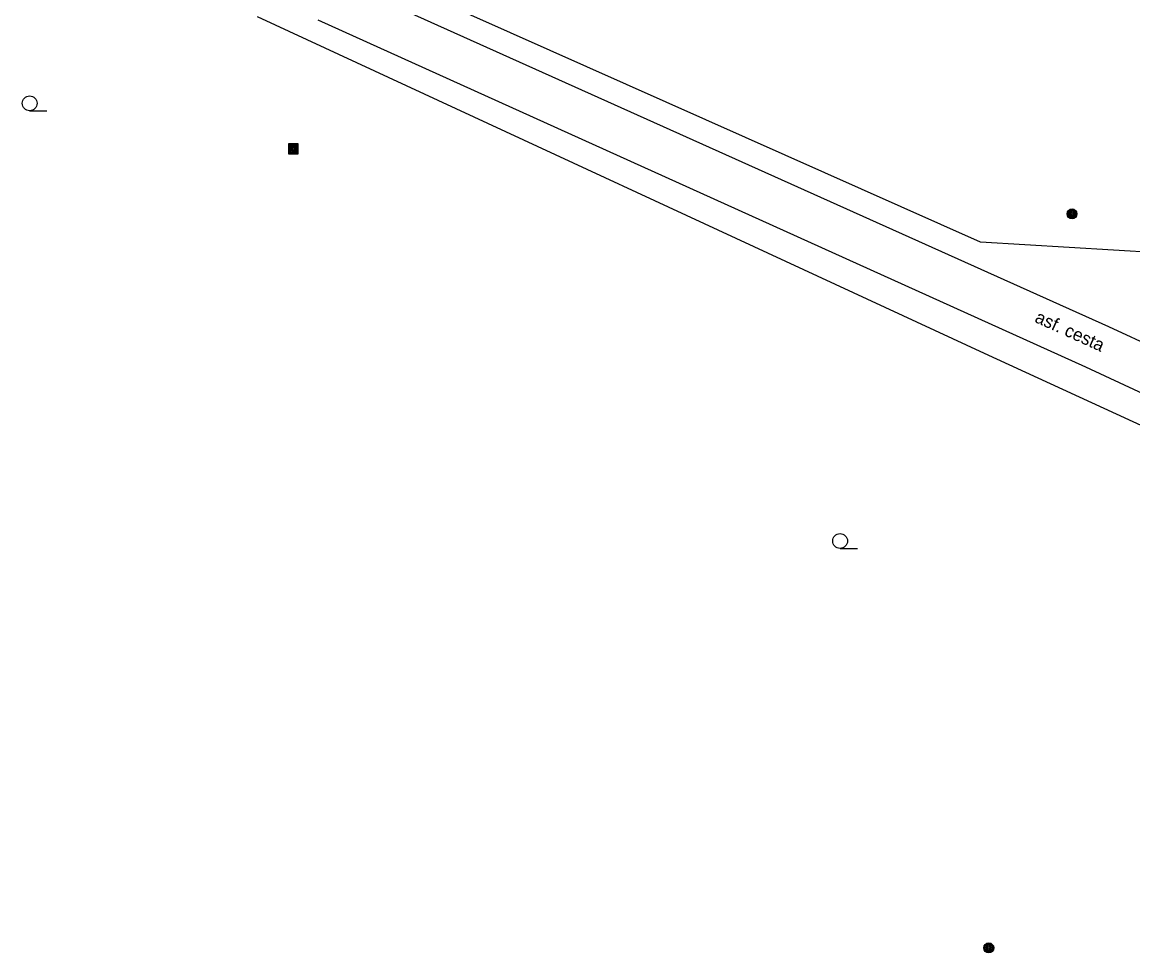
# Model space of a CAD drawing. Extents: x -538441 to -536770, y -1181008 to -1179809.
# Drawn here: x -537623 to -537566.8, y -1180346.7 to -1180299.6 of the extents above; entities that cross this region are included whole.
import ezdxf

# ---------------------------------------------------------------- set-up
doc = ezdxf.new("R2010")
doc.units = 0
for name, color, linetype in [('Vrstva 10', 7, 'Continuous'), ('Vrstva 23', 7, 'Continuous'), ('Vrstva 25', 7, 'Continuous'), ('Vrstva 36', 7, 'Continuous'), ('Vrstva 40', 7, 'Continuous'), ('Vrstva 7', 7, 'Continuous')]:
    doc.layers.add(name, color=color, linetype=linetype)

msp = doc.modelspace()

# ---------------------------------------------------------------- linework, layer by layer
at = {"layer": 'Vrstva 10'}
for p, q in [((-537568.01, -1180314.99), (-537606.97, -1180297.48)), ((-537608.03, -1180299.46), (-537569.18, -1180317.01)), ((-537523.46, -1180335.49), (-537568.01, -1180314.99)), ((-537569.18, -1180317.01), (-537538.49, -1180331.34))]:
    msp.add_line(p, q, dxfattribs=at)
at = {"layer": 'Vrstva 23'}
for p, q in [((-537574.5, -1180310.7), (-537606.15, -1180296.6)), ((-537556.5, -1180311.8), (-537574.5, -1180310.7))]:
    msp.add_line(p, q, dxfattribs=at)
at = {"layer": 'Vrstva 25'}
for points in [[(-537609.52, -1180306.23), (-537609.02, -1180306.23), (-537609.02, -1180305.73), (-537609.52, -1180305.73)], [(-537609.47, -1180306.18), (-537609.07, -1180306.18), (-537609.07, -1180305.78), (-537609.47, -1180305.78)], [(-537609.421, -1180306.13), (-537609.12, -1180306.131), (-537609.119, -1180305.83), (-537609.42, -1180305.829)], [(-537609.37, -1180306.08), (-537609.17, -1180306.08), (-537609.17, -1180305.88), (-537609.37, -1180305.88)], [(-537609.32, -1180306.03), (-537609.22, -1180306.03), (-537609.22, -1180305.93), (-537609.32, -1180305.93)]]:
    msp.add_lwpolyline(points, close=True, dxfattribs=at)
for centre, radius in [((-537569.87, -1180309.27), 0.25), ((-537569.87, -1180309.27), 0.2), ((-537569.87, -1180309.27), 0.15), ((-537569.87, -1180309.27), 0.1), ((-537569.87, -1180309.27), 0.05), ((-537574.08, -1180346.4), 0.25), ((-537574.08, -1180346.4), 0.2), ((-537574.08, -1180346.4), 0.15), ((-537574.08, -1180346.4), 0.1), ((-537574.08, -1180346.4), 0.05)]:
    msp.add_circle(centre, radius, dxfattribs=at)
at = {"layer": 'Vrstva 36'}
for p, q in [((-537622.612, -1180304.052), (-537621.737, -1180304.052)), ((-537581.605, -1180326.196), (-537580.73, -1180326.196))]:
    msp.add_line(p, q, dxfattribs=at)
for centre in [(-537622.612, -1180303.677), (-537581.605, -1180325.821)]:
    msp.add_circle(centre, 0.375, dxfattribs=at)
at = {"layer": 'Vrstva 7'}
for p, q in [((-537574.29, -1180316.33), (-537611.08, -1180299.31)), ((-537537.42, -1180333.32), (-537574.29, -1180316.33))]:
    msp.add_line(p, q, dxfattribs=at)

# ---------------------------------------------------------------- texts
at = {"layer": 'Vrstva 40'}
msp.add_text('asf. cesta', height=0.65, rotation=335.6895, dxfattribs=at).set_placement((-537571.802, -1180314.724))

doc.saveas('drawing.dxf')
